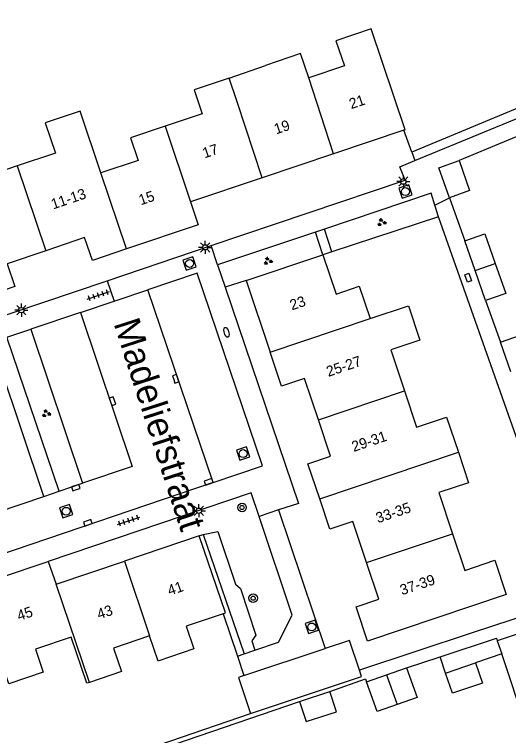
# Model space of a CAD drawing. Extents: x 136000 to 138005, y 398500 to 400500.
# Drawn here: x 137488.4 to 137535.5, y 398734.6 to 398803.4 of the extents above; entities that cross this region are included whole.
import ezdxf

# ---------------------------------------------------------------- set-up
doc = ezdxf.new("R2010")
doc.units = 0
for name, color, linetype in [('gg-afsc-erfafscheiding', 7, 'Continuous'), ('gg-afsc-hekwerk', 7, 'Continuous'), ('gg-afsc-muur', 7, 'Continuous'), ('gg-anno-huisnummerreeks BGT', 7, 'Continuous'), ('gg-anno-openbare ruimte label', 7, 'Continuous'), ('gg-bbg-bijgebouw', 7, 'Continuous'), ('gg-bbg-gedigitaliseerde bebouwing', 7, 'Continuous'), ('gg-bbg-hoofdgebouw', 7, 'Continuous'), ('gg-bbg-tussenscheiding', 7, 'Continuous'), ('gg-knt-verharding', 7, 'Continuous'), ('gg-knt-verharding nz', 7, 'Continuous'), ('gt-grn-groengrens', 7, 'Continuous'), ('gt-grn-vlakafsluiter', 7, 'Continuous'), ('gt-grn-weggrens', 7, 'Continuous'), ('gt-symb-boom', 7, 'Continuous'), ('gt-symb-brandkraan', 7, 'Continuous'), ('gt-symb-groenvak', 7, 'Continuous'), ('gt-symb-kolk', 7, 'Continuous'), ('gt-symb-kolk center center', 7, 'Continuous'), ('gt-symb-lichtmast', 7, 'Continuous'), ('gt-symb-rioolschacht', 7, 'Continuous'), ('gt-symb-tegel verharding', 7, 'Continuous')]:
    doc.layers.add(name, color=color, linetype=linetype)

# ---------------------------------------------------------------- blocks, each defined once
blk = doc.blocks.new('gt0-GRVAK')
at = {"layer": 'gt-symb-groenvak'}
for p, q in [((-0.11, 0.189), (-0.228, 0.24)), ((-0.182, 0.153), (0.088, 0.153)), ((-0.091, 0.211), (-0.156, 0.322)), ((-0.047, 0.214), (-0.047, 0.393)), ((-0.004, 0.211), (0.061, 0.322)), ((0.015, 0.189), (0.133, 0.24)), ((0.262, -0.052), (0.197, 0.059)), ((0.305, -0.049), (0.305, 0.13)), ((0.349, -0.052), (0.414, 0.059)), ((-0.245, -0.228), (-0.363, -0.177)), ((-0.318, -0.264), (-0.047, -0.264)), ((-0.226, -0.206), (-0.291, -0.095)), ((-0.183, -0.203), (-0.183, -0.024)), ((-0.139, -0.206), (-0.074, -0.095)), ((-0.12, -0.228), (-0.002, -0.177)), ((0.243, -0.074), (0.125, -0.023)), ((0.17, -0.11), (0.441, -0.11)), ((0.368, -0.074), (0.486, -0.023))]:
    blk.add_line(p, q, dxfattribs=at)
blk = doc.blocks.new('gt0-LMAST')
at = {"layer": 'gt-symb-lichtmast'}
for p, q in [((-0.182, 0.173), (-0.447, 0.438)), ((-0.005, 0.246), (-0.005, 0.621)), ((0.172, 0.173), (0.437, 0.438)), ((-0.255, -0.004), (-0.63, -0.004)), ((-0.182, -0.181), (-0.447, -0.446)), ((-0.005, -0.254), (-0.005, -0.629)), ((0.437, -0.446), (0.172, -0.181)), ((0.245, -0.004), (0.62, -0.004))]:
    blk.add_line(p, q, dxfattribs=at)
blk.add_circle((-0.005, -0.004), 0.25, dxfattribs=at)
blk = doc.blocks.new('gt0-RS')
at = {"layer": 'gt-symb-rioolschacht'}
blk.add_lwpolyline([(-0.5, -0.5), (0.5, -0.5), (0.5, 0.5), (-0.5, 0.5)], close=True, dxfattribs=at)
blk.add_circle((0, 0), 0.375, dxfattribs=at)
blk = doc.blocks.new('gt0-KOLKCC')
at = {"layer": 'gt-symb-kolk center center'}
blk.add_lwpolyline([(-0.375, 0.2), (0.375, 0.2), (0.375, -0.2), (-0.375, -0.2)], close=True, dxfattribs=at)
blk = doc.blocks.new('gt0-BOOM')
at = {"layer": 'gt-symb-boom'}
for radius in [0.4, 0.2]:
    blk.add_circle((0, 0), radius, dxfattribs=at)
blk = doc.blocks.new('gt0-BR')
at = {"layer": 'gt-symb-brandkraan'}
for centre, radius, start, end in [((-0.244, 0), 0.206, 107.56694, 252.43307), ((0.599, -2.664), 3, 106.89205, 107.56694), ((0, -0.691), 0.938, 73.10799, 106.89205), ((-0.599, -2.664), 3, 72.43309, 73.10799), ((0.244, 0), 0.206, 287.56695, 72.43309), ((0.599, 2.664), 3, 252.43307, 253.10797), ((0, 0.691), 0.938, 253.10797, 286.89206), ((-0.599, 2.664), 3, 286.89206, 287.56695)]:
    blk.add_arc(centre, radius, start, end, dxfattribs=at)
blk = doc.blocks.new('gt0-TEG1')
at = {"layer": 'gt-symb-tegel verharding'}
for p, q in [((-1.125, 0), (1.125, 0)), ((-0.9, -0.25), (-0.9, 0.25)), ((-0.45, -0.25), (-0.45, 0.25)), ((0, -0.25), (0, 0.25)), ((0.45, -0.25), (0.45, 0.25)), ((0.9, -0.25), (0.9, 0.25))]:
    blk.add_line(p, q, dxfattribs=at)
blk = doc.blocks.new('gt0-KOLK')
at = {"layer": 'gt-symb-kolk'}
blk.add_lwpolyline([(0, 0), (0.375, 0), (0.375, 0.4), (-0.375, 0.4), (-0.375, 0), (0, 0)], dxfattribs=at)

msp = doc.modelspace()

# ---------------------------------------------------------------- linework, layer by layer
at = {"layer": 'gg-afsc-erfafscheiding'}
for p, q in [((137538.659, 398792.764), (137530.803, 398789.481)), ((137529.893, 398785.946), (137531.345, 398781.831)), ((137540.187, 398751.946), (137528.837, 398784.132)), ((137533.342, 398776.142), (137534.747, 398772.173)), ((137508.322, 398746.266), (137509.679, 398742.22)), ((137509.679, 398742.22), (137510.303, 398740.358))]:
    msp.add_line(p, q, dxfattribs=at)
msp.add_lwpolyline([(137541.471, 398747.537), (137532.047, 398744.448), (137521.319, 398740.872)], dxfattribs=at)
at = {"layer": 'gg-afsc-hekwerk'}
for p, q in [((137528.995, 398742.167), (137534.361, 398743.933)), ((137525.799, 398741.115), (137528.995, 398742.167)), ((137529.512, 398740.597), (137528.995, 398742.167)), ((137534.872, 398742.444), (137532.368, 398741.576)), ((137537.667, 398733.999), (137534.872, 398742.444)), ((137496.882, 398731.495), (137515.601, 398737.906)), ((137489.05, 398729.27), (137510.94, 398736.75))]:
    msp.add_line(p, q, dxfattribs=at)
msp.add_lwpolyline([(137518.479, 398738.848), (137521.889, 398740.063), (137521.99, 398739.78)], dxfattribs=at)
at = {"layer": 'gg-afsc-muur'}
for p, q in [((137526.304, 398790.304), (137525.549, 398792.379)), ((137528.837, 398784.132), (137518.691, 398780.775)), ((137518.691, 398780.775), (137517.83, 398780.49))]:
    msp.add_line(p, q, dxfattribs=at)
msp.add_lwpolyline([(137549.836, 398805.159), (137549.525, 398800.044), (137547.49, 398799.209), (137547.529, 398799.118), (137526.304, 398790.304)], dxfattribs=at)
at = {"layer": 'gg-bbg-bijgebouw'}
for p, q in [((137528.888, 398788.808), (137530.803, 398789.481)), ((137529.893, 398785.946), (137528.888, 398788.808)), ((137532.344, 398778.987), (137531.345, 398781.831)), ((137533.342, 398776.142), (137532.344, 398778.987)), ((137535.747, 398769.328), (137534.747, 398772.173)), ((137510.303, 398740.358), (137518.049, 398742.945)), ((137529.512, 398740.597), (137532.368, 398741.576)), ((137521.99, 398739.78), (137523.895, 398740.448)), ((137523.895, 398740.448), (137525.799, 398741.115)), ((137515.601, 398737.906), (137518.479, 398738.848))]:
    msp.add_line(p, q, dxfattribs=at)
for points in [[(137530.803, 398789.481), (137531.808, 398786.619), (137529.893, 398785.946)], [(137531.345, 398781.831), (137533.26, 398782.503), (137534.259, 398779.659)], [(137534.259, 398779.659), (137535.257, 398776.814), (137533.342, 398776.142)], [(137534.747, 398772.173), (137536.662, 398772.846), (137537.662, 398770.001)], [(137521.319, 398740.872), (137520.37, 398743.72), (137518.049, 398742.945)], [(137532.368, 398741.576), (137533.036, 398739.653), (137530.18, 398738.675), (137529.512, 398740.597)], [(137510.94, 398736.75), (137521.52, 398740.27), (137521.319, 398740.872)], [(137525.799, 398741.115), (137526.815, 398738.266), (137524.911, 398737.598)], [(137510.303, 398740.358), (137509.8, 398740.19), (137510.94, 398736.75)], [(137524.911, 398737.598), (137523.006, 398736.93), (137521.99, 398739.78)], [(137515.601, 398737.906), (137516.234, 398735.973), (137519.112, 398736.915), (137518.479, 398738.848)]]:
    msp.add_lwpolyline(points, dxfattribs=at)
at = {"layer": 'gg-bbg-gedigitaliseerde bebouwing'}
msp.add_line((137508.897, 398797.35), (137512.355, 398798.558), dxfattribs=at)
for points in [[(137525.67, 398792.42), (137522.442, 398802.043), (137519.071, 398800.911), (137519.875, 398798.518), (137516.486, 398797.379)], [(137516.486, 398797.379), (137515.711, 398799.686), (137512.355, 398798.558)], [(137508.897, 398797.35), (137505.56, 398796.23), (137506.325, 398793.952), (137502.795, 398792.766)], [(137496.664, 398788.315), (137494.687, 398794.199), (137491.362, 398793.082), (137492.332, 398790.196), (137488.705, 398788.978)], [(137502.795, 398792.766), (137499.496, 398791.658), (137500.218, 398789.509), (137496.664, 398788.315)], [(137488.705, 398788.978), (137485.078, 398787.759), (137484.127, 398790.591), (137480.8, 398789.474), (137485.19, 398776.36)], [(137495.572, 398739.71), (137495.326, 398739.627), (137493.838, 398744.027), (137490.438, 398742.877), (137491.18, 398740.683), (137487.905, 398739.576), (137487.143, 398741.828)], [(137501.31, 398744.154), (137497.876, 398742.993), (137498.636, 398740.746), (137495.572, 398739.71)], [(137502.19, 398741.76), (137502.126, 398741.738), (137501.31, 398744.154)]]:
    msp.add_lwpolyline(points, dxfattribs=at)
at = {"layer": 'gg-bbg-hoofdgebouw'}
for p, q in [((137525.549, 398792.379), (137518.852, 398790.129)), ((137525.549, 398792.379), (137525.67, 398792.42)), ((137518.852, 398790.129), (137512.036, 398787.84)), ((137512.036, 398787.84), (137505.22, 398785.55)), ((137510.51, 398778.06), (137517.83, 398780.49)), ((137510.51, 398778.06), (137512.804, 398771.226)), ((137506.05, 398753.68), (137498.914, 398751.28)), ((137484.744, 398748.922), (137491.66, 398751.26)), ((137491.66, 398751.26), (137492.4, 398749.09)), ((137492.4, 398749.09), (137498.914, 398751.28))]:
    msp.add_line(p, q, dxfattribs=at)
for points in [[(137505.22, 398785.55), (137505.94, 398783.37), (137499.118, 398781.062)], [(137499.118, 398781.062), (137495.86, 398779.96), (137495.12, 398782.14), (137491.43, 398780.89)], [(137491.43, 398780.89), (137487.74, 398779.64), (137488.48, 398777.47), (137485.19, 398776.36)], [(137517.83, 398780.49), (137519.09, 398776.73), (137521.29, 398777.5), (137522.32, 398774.42)], [(137522.32, 398774.42), (137526, 398775.64), (137527.08, 398772.371)], [(137527.08, 398772.371), (137524.291, 398771.437), (137525.601, 398767.52)], [(137517.401, 398764.75), (137516.07, 398768.69), (137513.9, 398767.96), (137512.804, 398771.226)], [(137525.601, 398767.52), (137526.762, 398764.052), (137529.621, 398765.009), (137530.738, 398761.672)], [(137517.524, 398757.21), (137516.39, 398760.57), (137518.57, 398761.29), (137517.401, 398764.75)], [(137530.738, 398761.672), (137531.715, 398758.752), (137528.891, 398757.812), (137530.195, 398753.888)], [(137521.991, 398751.143), (137520.68, 398755.06), (137518.5, 398754.32), (137517.524, 398757.21)], [(137508.322, 398746.266), (137508.54, 398746.34), (137506.05, 398753.68)], [(137530.195, 398753.888), (137531.353, 398750.401), (137534.204, 398751.363), (137535.302, 398748.109), (137522.08, 398743.65)], [(137522.08, 398743.65), (137520.99, 398746.93), (137523.16, 398747.65), (137521.991, 398751.143)], [(137508.322, 398746.266), (137504.8, 398745.07), (137505.53, 398742.9), (137502.19, 398741.76)]]:
    msp.add_lwpolyline(points, dxfattribs=at)
at = {"layer": 'gg-bbg-tussenscheiding'}
for p, q in [((137509.656, 398795.09), (137508.897, 398797.35)), ((137518.852, 398790.129), (137516.486, 398797.379)), ((137512.036, 398787.84), (137509.656, 398795.09)), ((137502.795, 398792.766), (137505.22, 398785.55)), ((137488.705, 398788.978), (137491.43, 398780.89)), ((137499.118, 398781.062), (137496.664, 398788.315)), ((137532.344, 398778.987), (137534.259, 398779.659)), ((137512.804, 398771.226), (137522.32, 398774.42)), ((137517.401, 398764.75), (137525.601, 398767.52)), ((137517.524, 398757.21), (137530.738, 398761.672)), ((137521.991, 398751.143), (137530.195, 398753.888)), ((137498.914, 398751.28), (137501.31, 398744.154)), ((137495.572, 398739.71), (137492.4, 398749.09)), ((137523.895, 398740.448), (137524.911, 398737.598))]:
    msp.add_line(p, q, dxfattribs=at)
at = {"layer": 'gg-knt-verharding'}
for p, q in [((137526.602, 398789.483), (137551.694, 398799.904)), ((137528.139, 398786.363), (137517.968, 398782.956)), ((137528.488, 398785.248), (137528.139, 398786.363)), ((137528.837, 398784.132), (137528.488, 398785.248)), ((137517.114, 398782.669), (137507.8, 398779.55)), ((137517.83, 398780.49), (137517.114, 398782.669)), ((137518.691, 398780.775), (137517.968, 398782.956)), ((137497.277, 398778.03), (137507.185, 398781.372)), ((137507.8, 398779.55), (137508.525, 398777.402)), ((137497.932, 398776.09), (137501.144, 398777.169)), ((137494.72, 398775.01), (137497.932, 398776.09)), ((137494.72, 398775.01), (137489.98, 398773.42)), ((137489.98, 398773.42), (137494.929, 398758.713)), ((137507.363, 398758.768), (137475.24, 398747.88)), ((137492.69, 398757.952), (137494.929, 398758.713)), ((137491.237, 398757.459), (137492.69, 398757.952)), ((137484.191, 398755.065), (137491.237, 398757.459)), ((137513.6, 398756.16), (137518.049, 398742.945)), ((137510.342, 398742.443), (137511.347, 398742.782)), ((137509.679, 398742.22), (137510.342, 398742.443))]:
    msp.add_line(p, q, dxfattribs=at)
for points in [[(137507.185, 398781.372), (137525.68, 398787.61), (137525.15, 398788.88), (137526.602, 398789.483)], [(137507.363, 398758.768), (137512.08, 398760.36), (137505.863, 398778.76), (137501.144, 398777.169)], [(137479.85, 398769.01), (137486.01, 398771.11), (137485.06, 398773.91), (137497.277, 398778.03)], [(137508.525, 398777.402), (137515.49, 398756.78), (137513.6, 398756.16)], [(137492.69, 398757.952), (137487.71, 398772.64), (137489.98, 398773.42)], [(137491.237, 398757.459), (137487.06, 398769.87), (137478.73, 398767.05), (137481.9, 398757.64), (137483.17, 398758.06), (137484.191, 398755.065)], [(137511.753, 398755.546), (137511, 398757.81), (137491.66, 398751.26)], [(137511.347, 398742.782), (137513.6, 398743.54), (137514.89, 398746.11), (137511.753, 398755.546)], [(137541.767, 398747.483), (137541.79, 398747.415), (137537.585, 398745.99), (137537.992, 398744.857), (137534.441, 398743.691)], [(137534.441, 398743.691), (137534.432, 398743.688), (137534.872, 398742.444)]]:
    msp.add_lwpolyline(points, dxfattribs=at)
at = {"layer": 'gg-knt-verharding nz'}
msp.add_line((137507.363, 398758.768), (137501.144, 398777.169), dxfattribs=at)
msp.add_lwpolyline([(137494.72, 398775.01), (137499.66, 398760.32), (137494.929, 398758.713)], dxfattribs=at)
at = {"layer": 'gt-grn-groengrens'}
for p, q in [((137506.05, 398753.68), (137506.429, 398753.809)), ((137506.429, 398753.809), (137510.342, 398742.443)), ((137534.361, 398743.933), (137534.441, 398743.691))]:
    msp.add_line(p, q, dxfattribs=at)
msp.add_lwpolyline([(137506.429, 398753.809), (137507.803, 398754.116), (137509.505, 398749.097), (137509.966, 398748.673), (137511.428, 398744.233), (137511.044, 398743.682), (137511.347, 398742.782)], dxfattribs=at)
at = {"layer": 'gt-grn-vlakafsluiter'}
for p, q in [((137526.304, 398790.304), (137526.602, 398789.483)), ((137528.488, 398785.248), (137529.893, 398785.946)), ((137510.51, 398778.06), (137508.525, 398777.402))]:
    msp.add_line(p, q, dxfattribs=at)
at = {"layer": 'gt-grn-weggrens'}
for p, q in [((137517.968, 398782.956), (137517.114, 398782.669)), ((137507.8, 398779.55), (137507.185, 398781.372)), ((137497.277, 398778.03), (137497.932, 398776.09)), ((137513.6, 398756.16), (137511.753, 398755.546))]:
    msp.add_line(p, q, dxfattribs=at)

# ---------------------------------------------------------------- block references
at = {"layer": 'gt-symb-boom'}
for p in [(137510.126, 398756.397), (137511.185, 398747.745)]:
    msp.add_blockref('gt0-BOOM', p, dxfattribs=at)
at = {"layer": 'gt-symb-brandkraan', "rotation": -71.5106736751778}
msp.add_blockref('gt0-BR', (137508.642, 398773.111), dxfattribs=at)
at = {"layer": 'gt-symb-groenvak'}
for p in [(137523.422, 398783.588), (137512.584, 398779.901), (137491.461, 398765.359)]:
    msp.add_blockref('gt0-GRVAK', p, dxfattribs=at)
at = {"layer": 'gt-symb-kolk'}
for p, rotation in [((137503.608, 398768.614), -71.40202220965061), ((137497.589, 398766.468), -71.40202220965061), ((137507.007, 398758.652), 18.724868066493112), ((137494.357, 398758.097), 18.724868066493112), ((137495.488, 398754.747), 18.724868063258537)]:
    msp.add_blockref('gt0-KOLK', p, dxfattribs=dict(at, rotation=rotation))
at = {"layer": 'gt-symb-kolk center center', "rotation": -70.04653897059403}
msp.add_blockref('gt0-KOLKCC', (137531.679, 398778.313), dxfattribs=at)
at = {"layer": 'gt-symb-lichtmast'}
for p in [(137525.501, 398787.484), (137506.619, 398781.212), (137489.095, 398775.223), (137506.02, 398756.093)]:
    msp.add_blockref('gt0-LMAST', p, dxfattribs=at)
at = {"layer": 'gt-symb-rioolschacht'}
for p, rotation in [((137525.697, 398786.529), 18.724868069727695), ((137505.124, 398779.673), 18.724868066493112), ((137510.226, 398761.539), -162.12657893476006), ((137493.363, 398756.035), 18.724868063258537), ((137516.766, 398745.003), 18.59797779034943)]:
    msp.add_blockref('gt0-RS', p, dxfattribs=dict(at, rotation=rotation))
at = {"layer": 'gt-symb-tegel verharding', "rotation": 18.543669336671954}
for p in [(137496.433, 398776.634), (137499.308, 398755.128)]:
    msp.add_blockref('gt0-TEG1', p, dxfattribs=at)

# ---------------------------------------------------------------- texts
at = {"layer": 'gg-anno-huisnummerreeks BGT'}
for s, rotation, p in [('21', 18.5, (137520.527, 398794.385)), ('19', 18.5, (137513.368, 398791.98)), ('17', 18.5, (137506.548, 398789.689)), ('11-13', 18.7, (137492.117, 398784.818)), ('15', 18.7, (137500.474, 398785.215)), ('23', 18.5, (137514.871, 398775.194)), ('25-27', 18.7, (137518.352, 398768.851)), ('29-31', 18.7, (137520.771, 398761.691)), ('33-35', 18.5, (137523.071, 398754.892)), ('37-39', 18.5, (137525.372, 398748.017)), ('41', 18.6, (137503.217, 398747.979)), ('45', 18.7, (137488.872, 398745.567)), ('43', 18.6, (137496.493, 398745.718))]:
    msp.add_text(s, height=1, rotation=rotation, dxfattribs=at).set_placement(p)
at = {"layer": 'gg-anno-openbare ruimte label'}
msp.add_text('Madeliefstraat', height=2.5, rotation=287.9, dxfattribs=at).set_placement((137497.871, 398773.963))

doc.saveas('drawing.dxf')
